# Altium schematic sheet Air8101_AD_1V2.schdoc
size 297 x 209 mm; Symbol: Drawing-Symbol_A4; Company: 嘉立创EDA; Version: V1.0; Page Size: A4; @Project Name: Air8101A; @Update Date: 2026-01-27; @Create Date: 2026-01-27; Device: Drawing-Symbol_A4; @Board Name: Board1; @Page Name: P1; @Create Time: 18:42:39; @Page Count: 1; @Page No: 1; @Schematic Name: Schematic1; @Update Time: 18:42:39; @Assembly Variant: Basic; Border: 1; Title Block Position: 3; Size: A4; Width: 1170; Height: 825; Region Start: 1; X Region Count: 6; Y Region Count: 4; Blade Width: 10; Title Block: 1
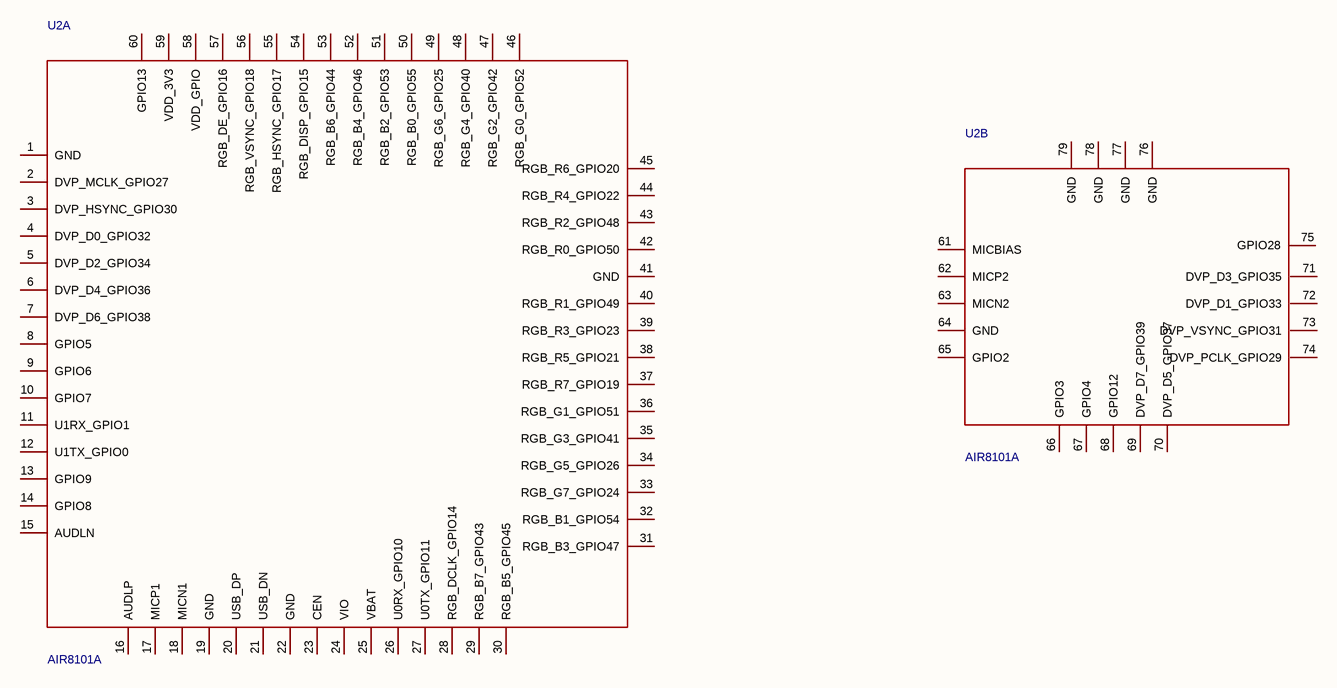
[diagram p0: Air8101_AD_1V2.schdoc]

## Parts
U2  AIR8101A  [AIR8101A-PADS]  (parts A,B of 2)

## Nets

Not connected (* = marked no-connect by the designer): U2 1(GND) 2(DVP_MCLK_GPIO27) 3(DVP_HSYNC_GPIO30) 4(DVP_D0_GPIO32) 5(DVP_D2_GPIO34) 6(DVP_D4_GPIO36) 7(DVP_D6_GPIO38) 8(GPIO5) 9(GPIO6) 10(GPIO7) 11(U1RX_GPIO1) 12(U1TX_GPIO0) 13(GPIO9) 14(GPIO8) 15(AUDLN) 16(AUDLP) 17(MICP1) 18(MICN1) 19(GND) 20(USB_DP) 21(USB_DN) 22(GND) 23(CEN) 24(VIO) 25(VBAT) 26(U0RX_GPIO10) 27(U0TX_GPIO11) 28(RGB_DCLK_GPIO14) 29(RGB_B7_GPIO43) 30(RGB_B5_GPIO45) 31(RGB_B3_GPIO47) 32(RGB_B1_GPIO54) 33(RGB_G7_GPIO24) 34(RGB_G5_GPIO26) 35(RGB_G3_GPIO41) 36(RGB_G1_GPIO51) 37(RGB_R7_GPIO19) 38(RGB_R5_GPIO21) 39(RGB_R3_GPIO23) 40(RGB_R1_GPIO49) 41(GND) 42(RGB_R0_GPIO50) 43(RGB_R2_GPIO48) 44(RGB_R4_GPIO22) 45(RGB_R6_GPIO20) 46(RGB_G0_GPIO52) 47(RGB_G2_GPIO42) 48(RGB_G4_GPIO40) 49(RGB_G6_GPIO25) 50(RGB_B0_GPIO55) 51(RGB_B2_GPIO53) 52(RGB_B4_GPIO46) 53(RGB_B6_GPIO44) 54(RGB_DISP_GPIO15) 55(RGB_HSYNC_GPIO17) 56(RGB_VSYNC_GPIO18) 57(RGB_DE_GPIO16) 58(VDD_GPIO) 59(VDD_3V3) 60(GPIO13) 61(MICBIAS) 62(MICP2) 63(MICN2) 64(GND) 65(GPIO2) 66(GPIO3) 67(GPIO4) 68(GPIO12) 69(DVP_D7_GPIO39) 70(DVP_D5_GPIO37) 71(DVP_D3_GPIO35) 72(DVP_D1_GPIO33) 73(DVP_VSYNC_GPIO31) 74(DVP_PCLK_GPIO29) 75(GPIO28) 76(GND) 77(GND) 78(GND) 79(GND)

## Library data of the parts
U2 = AIR8101A: Relevance: []; AddInBom: yes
